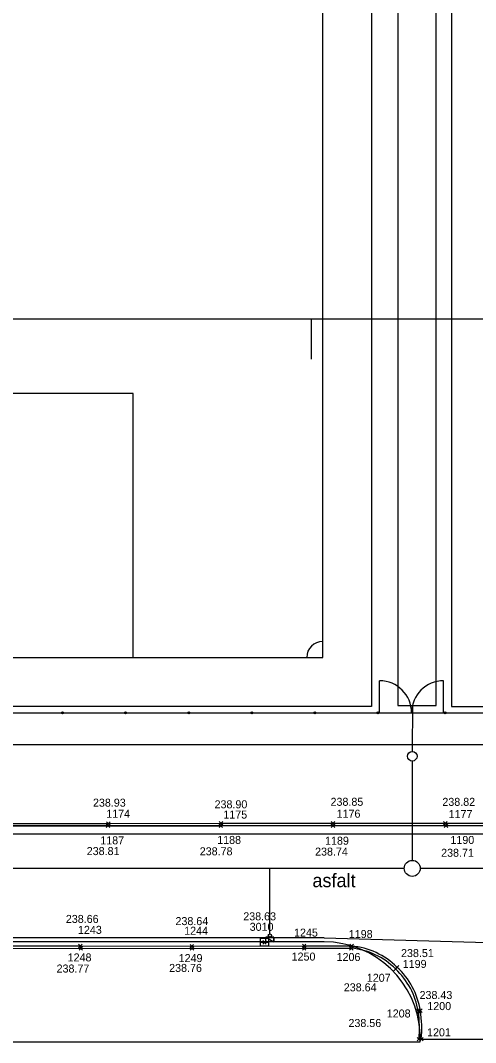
# Model space of a CAD drawing. Extents: x -264205 to -263615, y -1242401 to -1242031.
# Drawn here: x -264069.5 to -264041.1, y -1242315 to -1242251.2 of the extents above; entities that cross this region are included whole.
import ezdxf

# ---------------------------------------------------------------- set-up
doc = ezdxf.new("R2010")
doc.units = 0
for name, color, linetype in [('BODY_SYMBOL A CISLO_2-1', 7, 'Continuous'), ('BODY_VYSKA_2-1', 7, 'Continuous'), ('KOORDINACNA_SITUACIA_DSP', 7, 'Continuous'), ('POPIS', 7, 'Continuous'), ('PROJEKT_DRS_TDZ_VODOROVNE', 7, 'Continuous'), ('RAM_NA_TLAC_1-250_SITUACIA_2-1', 7, 'Continuous'), ('SO_20-1_OBRUBNIKY_DOLNA_HRANA', 7, 'Continuous'), ('SO_20-1_OBRUBNIKY_DOLNA_HRANA_POMOCNE', 7, 'Continuous'), ('SO_20-1_OBRUBNIKY_HORNA_HRANA', 7, 'Continuous'), ('SO_20-1_UV', 7, 'Continuous')]:
    doc.layers.add(name, color=color, linetype=linetype)

msp = doc.modelspace()

# ---------------------------------------------------------------- linework, layer by layer
at = {"layer": 'BODY_SYMBOL A CISLO_2-1'}
for p, q in [((-264043.073, -1242301.434), (-264042.852, -1242301.214)), ((-264042.852, -1242301.434), (-264043.073, -1242301.214)), ((-264064.132, -1242301.593), (-264063.91, -1242301.372)), ((-264063.91, -1242301.593), (-264064.132, -1242301.372)), ((-264064.109, -1242301.455), (-264063.888, -1242301.235)), ((-264063.888, -1242301.455), (-264064.109, -1242301.235)), ((-264057.089, -1242301.593), (-264056.867, -1242301.372)), ((-264056.867, -1242301.593), (-264057.089, -1242301.372)), ((-264057.084, -1242301.444), (-264056.863, -1242301.224)), ((-264056.863, -1242301.444), (-264057.084, -1242301.224)), ((-264050.088, -1242301.592), (-264049.867, -1242301.37)), ((-264049.867, -1242301.592), (-264050.088, -1242301.37)), ((-264050.087, -1242301.443), (-264049.866, -1242301.221)), ((-264049.866, -1242301.443), (-264050.087, -1242301.221)), ((-264043.031, -1242301.586), (-264042.81, -1242301.365)), ((-264042.81, -1242301.586), (-264043.031, -1242301.365)), ((-264054.362, -1242308.873), (-264054.141, -1242308.651)), ((-264054.141, -1242308.873), (-264054.362, -1242308.651)), ((-264065.855, -1242309.107), (-264065.633, -1242308.887)), ((-264065.633, -1242309.107), (-264065.855, -1242308.887)), ((-264065.829, -1242309.254), (-264065.608, -1242309.032)), ((-264065.608, -1242309.254), (-264065.829, -1242309.032)), ((-264058.894, -1242309.12), (-264058.674, -1242308.899)), ((-264058.674, -1242309.12), (-264058.894, -1242308.899)), ((-264058.889, -1242309.268), (-264058.667, -1242309.046)), ((-264058.667, -1242309.268), (-264058.889, -1242309.046)), ((-264051.889, -1242309.106), (-264051.668, -1242308.884)), ((-264051.668, -1242309.106), (-264051.889, -1242308.884)), ((-264051.883, -1242309.249), (-264051.661, -1242309.029)), ((-264051.661, -1242309.249), (-264051.883, -1242309.029)), ((-264048.944, -1242309.251), (-264048.723, -1242309.029)), ((-264048.723, -1242309.251), (-264048.944, -1242309.029)), ((-264048.922, -1242309.106), (-264048.701, -1242308.886)), ((-264048.701, -1242309.106), (-264048.922, -1242308.886)), ((-264046.176, -1242310.541), (-264045.954, -1242310.319)), ((-264045.954, -1242310.541), (-264046.176, -1242310.319)), ((-264046.092, -1242310.427), (-264045.871, -1242310.207)), ((-264045.871, -1242310.427), (-264046.092, -1242310.207)), ((-264044.764, -1242313.183), (-264044.543, -1242312.961)), ((-264044.543, -1242313.183), (-264044.764, -1242312.961)), ((-264044.629, -1242313.15), (-264044.408, -1242312.93)), ((-264044.408, -1242313.15), (-264044.629, -1242312.93)), ((-264044.712, -1242314.924), (-264044.491, -1242314.704)), ((-264044.491, -1242314.924), (-264044.712, -1242314.704)), ((-264044.573, -1242314.924), (-264044.351, -1242314.704)), ((-264044.351, -1242314.924), (-264044.573, -1242314.704))]:
    msp.add_line(p, q, dxfattribs=at)
at = {"layer": 'KOORDINACNA_SITUACIA_DSP'}
for p, q in [((-264050.618, -1242290.982), (-264050.618, -1242190.982)), ((-264045.927, -1242194.982), (-264045.927, -1242293.982)), ((-264043.527, -1242293.982), (-264043.527, -1242194.982)), ((-264062.458, -1242274.482), (-264102.778, -1242274.482)), ((-264062.458, -1242290.982), (-264062.458, -1242274.482)), ((-264114.618, -1242290.982), (-264050.618, -1242290.982)), ((-264047.068, -1242294.432), (-264047.068, -1242292.432)), ((-264043.068, -1242294.432), (-264043.068, -1242292.432)), ((-264045.927, -1242293.982), (-264043.527, -1242293.982)), ((-264045.017, -1242293.982), (-264045.027, -1242296.847)), ((-264118.068, -1242294.432), (-264045.118, -1242294.432)), ((-264066.802, -1242294.432), (-264066.922, -1242294.432)), ((-264066.862, -1242294.492), (-264066.862, -1242294.372)), ((-264062.863, -1242294.432), (-264062.983, -1242294.432)), ((-264062.923, -1242294.492), (-264062.923, -1242294.372)), ((-264058.924, -1242294.432), (-264059.044, -1242294.432)), ((-264058.984, -1242294.492), (-264058.984, -1242294.372)), ((-264054.986, -1242294.432), (-264055.106, -1242294.432)), ((-264055.046, -1242294.492), (-264055.046, -1242294.372)), ((-264051.047, -1242294.432), (-264051.167, -1242294.432)), ((-264051.107, -1242294.492), (-264051.107, -1242294.372)), ((-264047.108, -1242294.432), (-264047.228, -1242294.432)), ((-264047.168, -1242294.492), (-264047.168, -1242294.372)), ((-264045.568, -1242294.432), (-264044.568, -1242294.432)), ((-264045.118, -1242294.432), (-263972.068, -1242294.432)), ((-264042.908, -1242294.432), (-264043.028, -1242294.432)), ((-264042.968, -1242294.492), (-264042.968, -1242294.372)), ((-264045.027, -1242297.447), (-264045.027, -1242303.647)), ((-263971.068, -1242301.482), (-264112.961, -1242301.482)), ((-264045.527, -1242304.147), (-264094.527, -1242304.147)), ((-264053.913, -1242308.242), (-264053.913, -1242304.147)), ((-264004.396, -1242304.147), (-264044.527, -1242304.147)), ((-264050.531, -1242308.732), (-264119.75, -1242308.732)), ((-264054.163, -1242308.442), (-264053.663, -1242308.442)), ((-264054.163, -1242308.732), (-264054.163, -1242308.442)), ((-264054.163, -1242308.442), (-264053.663, -1242308.732)), ((-264054.163, -1242308.442), (-264053.663, -1242308.732)), ((-264053.663, -1242308.442), (-264054.163, -1242308.442)), ((-264053.663, -1242308.732), (-264054.163, -1242308.732)), ((-264053.663, -1242308.442), (-264053.663, -1242308.732)), ((-264053.663, -1242308.732), (-264053.663, -1242308.442)), ((-264044.531, -1242314.982), (-264044.531, -1242314.482)), ((-264115.886, -1242314.982), (-264044.531, -1242314.982))]:
    msp.add_line(p, q, dxfattribs=at)
for points in [[(-264117.668, -1242187.932), (-264047.568, -1242187.932), (-264047.568, -1242294.032), (-264117.668, -1242294.032)], [(-264042.568, -1242294.032), (-263972.468, -1242294.032), (-263972.468, -1242187.932), (-264042.568, -1242187.932)]]:
    msp.add_lwpolyline(points, close=True, dxfattribs=at)
msp.add_lwpolyline([(-263965.143, -1242296.432), (-264120.018, -1242296.432), (-264120.282, -1242296.432)], dxfattribs=at)
for centre, radius in [((-264066.862, -1242294.432), 0.06), ((-264062.923, -1242294.432), 0.06), ((-264058.984, -1242294.432), 0.06), ((-264055.046, -1242294.432), 0.06), ((-264051.107, -1242294.432), 0.06), ((-264047.168, -1242294.432), 0.06), ((-264042.968, -1242294.432), 0.06), ((-264045.027, -1242297.147), 0.3), ((-264045.027, -1242304.147), 0.5), ((-264053.913, -1242308.342), 0.1)]:
    msp.add_circle(centre, radius, dxfattribs=at)
for centre, radius, start, end in [((-264050.618, -1242290.982), 1, 90, 180), ((-264047.068, -1242294.432), 2, 0, 90), ((-264043.068, -1242294.432), 2, 90, 180), ((-264050.561, -1242314.769), 6.037, 2.72538, 89.71237)]:
    msp.add_arc(centre, radius, start, end, dxfattribs=at)
at = {"layer": 'PROJEKT_DRS_TDZ_VODOROVNE'}
for p, q in [((-264112.961, -1242301.982), (-263971.806, -1242301.982)), ((-264050.531, -1242308.482), (-264112.906, -1242308.482)), ((-264050.531, -1242308.482), (-264032.141, -1242309.015))]:
    msp.add_line(p, q, dxfattribs=at)
at = {"layer": 'RAM_NA_TLAC_1-250_SITUACIA_2-1'}
msp.add_line((-264051.333, -1242269.835), (-264051.333, -1242272.335), dxfattribs=at)
msp.add_lwpolyline([(-264151.333, -1242269.835), (-263718.833, -1242269.835), (-263718.833, -1242344.085), (-264151.333, -1242344.085)], close=True, dxfattribs=at)
at = {"layer": 'SO_20-1_OBRUBNIKY_DOLNA_HRANA'}
for points in [[(-264084.992, -1242301.468), (-264078.002, -1242301.482), (-264070.986, -1242301.489), (-264064.021, -1242301.482), (-264056.978, -1242301.482), (-264049.977, -1242301.481), (-264042.921, -1242301.475), (-264035.92, -1242301.469), (-264028.972, -1242301.456), (-264022.003, -1242301.442), (-264014.974, -1242301.438), (-264007.969, -1242301.429), (-264000.909, -1242301.426), (-263993.952, -1242301.425)], [(-264086.721, -1242308.982), (-264079.708, -1242308.985), (-264072.821, -1242308.988), (-264065.744, -1242308.997), (-264058.784, -1242309.009), (-264051.779, -1242308.995), (-264048.812, -1242308.996)]]:
    msp.add_lwpolyline(points, dxfattribs=at)
for centre, major_axis, ratio, start_param, end_param in [((-264049.236, -1242313.601), (-0.121, 4.623), 0.99973, 5.475924, 6.165207), ((-264049.204, -1242313.793), (-3.668, 3.021), 0.997623, 3.991062, 4.653737), ((-264048.266, -1242313.635), (-0.777, 5.296), 0.708679, 4.385578, 4.720857)]:
    msp.add_ellipse(centre, major_axis=major_axis, ratio=ratio, start_param=start_param, end_param=end_param, dxfattribs=at)
at = {"layer": 'SO_20-1_OBRUBNIKY_DOLNA_HRANA_POMOCNE'}
msp.add_line((-264044.462, -1242314.814), (-264038.521, -1242314.824), dxfattribs=at)
at = {"layer": 'SO_20-1_OBRUBNIKY_HORNA_HRANA'}
for points in [[(-264084.994, -1242301.327), (-264077.993, -1242301.335), (-264070.958, -1242301.339), (-264063.998, -1242301.345), (-264056.974, -1242301.334), (-264049.976, -1242301.332), (-264042.963, -1242301.324), (-264035.917, -1242301.32), (-264028.967, -1242301.31), (-264022.019, -1242301.3), (-264014.954, -1242301.285), (-264007.975, -1242301.28), (-264000.942, -1242301.277), (-263993.949, -1242301.276)], [(-264086.73, -1242309.126), (-264079.711, -1242309.131), (-264072.777, -1242309.148), (-264065.719, -1242309.143), (-264058.778, -1242309.157), (-264051.772, -1242309.139), (-264048.834, -1242309.14)]]:
    msp.add_lwpolyline(points, dxfattribs=at)
for centre, major_axis, ratio, start_param, end_param in [((-264049.219, -1242313.585), (0.537, 4.429), 0.999772, 5.618541, 6.31756), ((-264049.294, -1242313.843), (-3.584, 3.057), 0.997273, 4.013713, 4.66096), ((-264047.913, -1242313.599), (-0.698, 4.901), 0.666836, 4.368269, 4.724889)]:
    msp.add_ellipse(centre, major_axis=major_axis, ratio=ratio, start_param=start_param, end_param=end_param, dxfattribs=at)
at = {"layer": 'SO_20-1_UV'}
msp.add_line((-264054.252, -1242308.762), (-264054.252, -1242308.762), dxfattribs=at)
msp.add_lwpolyline([(-264054.502, -1242308.762), (-264054.502, -1242308.512), (-264054.002, -1242308.512), (-264054.002, -1242309.012), (-264054.502, -1242309.012), (-264054.502, -1242308.762), (-264054.002, -1242308.762)], dxfattribs=at)

# ---------------------------------------------------------------- texts
at = {"layer": 'BODY_SYMBOL A CISLO_2-1'}
for s, p in [('1174', (-264064.132, -1242300.985)), ('1175', (-264056.82, -1242301.039)), ('1176', (-264049.75, -1242300.985)), ('1177', (-264042.757, -1242301.009)), ('1187', (-264064.504, -1242302.65)), ('1188', (-264057.204, -1242302.623)), ('1189', (-264050.47, -1242302.671)), ('1190', (-264042.643, -1242302.623)), ('3010', (-264055.177, -1242308.05)), ('1243', (-264065.898, -1242308.239)), ('1244', (-264059.267, -1242308.296)), ('1245', (-264052.407, -1242308.411)), ('1198', (-264048.988, -1242308.5)), ('1248', (-264066.541, -1242309.961)), ('1249', (-264059.611, -1242310.003)), ('1250', (-264052.559, -1242309.908)), ('1206', (-264049.75, -1242309.935)), ('1199', (-264045.621, -1242310.368)), ('1207', (-264047.864, -1242311.232)), ('1200', (-264044.087, -1242312.999)), ('1208', (-264046.617, -1242313.462)), ('1201', (-264044.102, -1242314.639))]:
    msp.add_text(s, height=0.5, dxfattribs=at).set_placement(p)
at = {"layer": 'BODY_VYSKA_2-1'}
for s, p in [('238.93', (-264064.961, -1242300.296)), ('238.90', (-264057.369, -1242300.398)), ('238.85', (-264050.128, -1242300.24)), ('238.82', (-264043.146, -1242300.244)), ('238.81', (-264065.35, -1242303.319)), ('238.78', (-264058.294, -1242303.332)), ('238.74', (-264051.093, -1242303.352)), ('238.71', (-264043.224, -1242303.425)), ('238.63', (-264055.576, -1242307.394)), ('238.66', (-264066.654, -1242307.557)), ('238.64', (-264059.81, -1242307.693)), ('238.51', (-264045.727, -1242309.689)), ('238.77', (-264067.232, -1242310.655)), ('238.76', (-264060.205, -1242310.617)), ('238.64', (-264049.301, -1242311.828)), ('238.43', (-264044.57, -1242312.31)), ('238.56', (-264049.009, -1242314.058))]:
    msp.add_text(s, height=0.5, dxfattribs=at).set_placement(p)
at = {"layer": 'POPIS'}
msp.add_text('asfalt', height=0.8438, dxfattribs=at).set_placement((-264051.261, -1242305.325))

doc.saveas('drawing.dxf')
